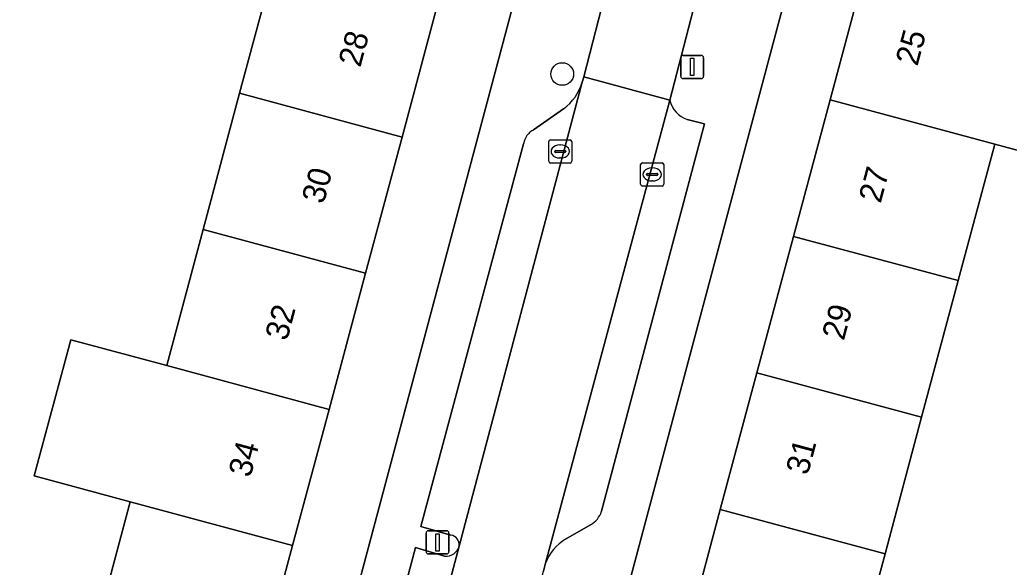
# Model space of a CAD drawing. Extents: x 163683 to 164494, y 382709 to 383872.
# Drawn here: x 163796.88 to 163839.7, y 383208.04 to 383231.71 of the extents above; entities that cross this region are included whole.
import ezdxf

# ---------------------------------------------------------------- set-up
doc = ezdxf.new("R2010")
doc.units = 0
for name, color, linetype in [('IMGEO_Boom', 7, 'Continuous'), ('IMGEO_Erf', 7, 'Continuous'), ('IMGEO_Kolk', 7, 'Continuous'), ('IMGEO_Lichtmast', 7, 'Continuous'), ('IMGEO_Pand', 7, 'Continuous'), ('IMGEO_Pand_nummerreeks', 7, 'Continuous'), ('IMGEO_Parkeervlak_open', 7, 'Continuous'), ('IMGEO_Rijbaan_lokaal_open', 7, 'Continuous'), ('IMGEO_Voetpad_open', 7, 'Continuous')]:
    doc.layers.add(name, color=color, linetype=linetype)

msp = doc.modelspace()

# ---------------------------------------------------------------- linework, layer by layer
at = {"layer": 'IMGEO_Boom'}
msp.add_circle((163820.356, 383229.363), 0.489, dxfattribs=at)
at = {"layer": 'IMGEO_Erf'}
for points in [[(163824.418, 383255.554), (163821.399, 383256.366), (163819.738, 383250.188), (163819.688, 383250), (163818.159, 383244.3), (163816.58, 383238.412), (163815.001, 383232.525), (163813.422, 383226.636), (163811.843, 383220.749), (163810.264, 383214.861), (163808.685, 383208.973), (163807.105, 383203.085), (163805.526, 383197.197), (163803.947, 383191.309), (163802.367, 383185.418), (163804.645, 383184.81)], [(163805.373, 383185.139), (163805.809, 383185.829), (163824.418, 383255.554)], [(163827.195, 383210.532), (163828.779, 383216.436), (163830.363, 383222.339), (163831.947, 383228.242), (163833.569, 383234.29), (163830.648, 383235.069), (163829.711, 383231.555), (163816.591, 383182.375)], [(163795.348, 383187.3), (163796.928, 383193.198), (163798.505, 383199.087), (163800.082, 383204.975), (163801.659, 383210.864), (163797.498, 383211.984), (163799.082, 383217.87), (163803.236, 383216.752), (163804.813, 383222.641), (163806.39, 383228.529), (163807.967, 383234.418)], [(163841.703, 383225.626), (163839.075, 383226.331), (163837.491, 383220.427), (163835.907, 383214.524), (163834.324, 383208.621), (163832.74, 383202.718), (163831.156, 383196.814), (163829.573, 383190.911), (163827.989, 383185.008), (163826.366, 383178.959), (163839.073, 383175.562), (163839.771, 383178.058), (163836.932, 383178.852), (163837.909, 383182.348), (163838.882, 383185.825), (163841.721, 383185.031)], [(163817.17, 383181.426), (163819.238, 383180.871), (163820.861, 383186.919), (163822.444, 383192.823), (163824.028, 383198.725), (163825.612, 383204.629), (163827.195, 383210.532)]]:
    msp.add_lwpolyline(points, dxfattribs=at)
at = {"layer": 'IMGEO_Kolk'}
for p, q in [((163819.769, 383225.588), (163819.769, 383226.44)), ((163819.844, 383226.514), (163820.696, 383226.514)), ((163820.77, 383226.44), (163820.77, 383225.588)), ((163820.028, 383226.008), (163820.028, 383226.02)), ((163820.466, 383225.971), (163820.068, 383225.971)), ((163820.071, 383226.057), (163820.469, 383226.057)), ((163820.257, 383226.294), (163820.282, 383226.294)), ((163820.512, 383226.02), (163820.512, 383226.008)), ((163820.696, 383225.514), (163819.844, 383225.514)), ((163820.28, 383225.734), (163820.255, 383225.734)), ((163823.823, 383225.52), (163824.675, 383225.52)), ((163823.748, 383224.594), (163823.748, 383225.446)), ((163824.05, 383225.063), (163824.448, 383225.063)), ((163824.236, 383225.3), (163824.261, 383225.3)), ((163824.749, 383225.446), (163824.749, 383224.594)), ((163824.007, 383225.014), (163824.007, 383225.026)), ((163824.445, 383224.977), (163824.047, 383224.977)), ((163824.259, 383224.74), (163824.234, 383224.74)), ((163824.491, 383225.026), (163824.491, 383225.014)), ((163824.675, 383224.52), (163823.823, 383224.52))]:
    msp.add_line(p, q, dxfattribs=at)
for points in [[(163819.769, 383225.588), (163819.769, 383226.44)], [(163819.844, 383226.514), (163820.696, 383226.514)], [(163820.77, 383226.44), (163820.77, 383225.588)], [(163820.696, 383225.514), (163819.844, 383225.514)], [(163823.823, 383225.52), (163824.675, 383225.52)], [(163823.748, 383224.594), (163823.748, 383225.446)], [(163824.749, 383225.446), (163824.749, 383224.594)], [(163824.675, 383224.52), (163823.823, 383224.52)]]:
    msp.add_lwpolyline(points, dxfattribs=at)
for centre, radius, start, end in [((163819.846, 383226.438), 0.0765, 91.552, 178.448), ((163819.846, 383226.438), 0.0765, 91.552, 178.448), ((163820.694, 383226.438), 0.0765, 1.552, 88.448), ((163820.694, 383226.438), 0.0765, 1.552, 88.448), ((163820.068, 383226.017), 0.0403, 85.8775, 175.7526), ((163820.065, 383226.007), 0.0366, 178.938, 274.7102), ((163820.469, 383226.014), 0.043, 264.8664, 352.4533), ((163820.473, 383226.019), 0.0386, 1.7309, 96.639), ((163819.846, 383225.59), 0.0765, 181.552, 268.448), ((163819.846, 383225.59), 0.0765, 181.552, 268.448), ((163820.694, 383225.59), 0.0765, 271.552, 358.448), ((163820.694, 383225.59), 0.0765, 271.552, 358.448), ((163823.825, 383225.444), 0.0765, 91.552, 178.448), ((163823.825, 383225.444), 0.0765, 91.552, 178.448), ((163824.673, 383225.444), 0.0765, 1.552, 88.448), ((163824.673, 383225.444), 0.0765, 1.552, 88.448), ((163824.047, 383225.023), 0.0403, 85.8775, 175.7526), ((163824.452, 383225.025), 0.0386, 1.7309, 96.639), ((163824.044, 383225.013), 0.0366, 178.938, 274.7102), ((163824.448, 383225.02), 0.043, 264.8664, 352.4533), ((163823.825, 383224.596), 0.0765, 181.552, 268.448), ((163823.825, 383224.596), 0.0765, 181.552, 268.448), ((163824.673, 383224.596), 0.0765, 271.552, 358.448), ((163824.673, 383224.596), 0.0765, 271.552, 358.448)]:
    msp.add_arc(centre, radius, start, end, dxfattribs=at)
for centre, major_axis, ratio, start_param, end_param in [((163820.256, 383226.014), (-0.387, 0.002), 0.722429, 4.712389, 7.853982), ((163820.281, 383226.014), (-0.39, 0.002), 0.717154, 1.570796, 4.712389), ((163824.235, 383225.02), (-0.387, 0.002), 0.722429, 4.712389, 7.853982), ((163824.26, 383225.02), (-0.39, 0.002), 0.717154, 1.570796, 4.712389)]:
    msp.add_ellipse(centre, major_axis=major_axis, ratio=ratio, start_param=start_param, end_param=end_param, dxfattribs=at)
at = {"layer": 'IMGEO_Lichtmast'}
for p, q in [((163825.482, 383229.268), (163825.482, 383230.068)), ((163825.482, 383230.068), (163825.482, 383229.268)), ((163825.582, 383230.168), (163826.372, 383230.168)), ((163826.372, 383230.168), (163825.582, 383230.168)), ((163826.472, 383230.068), (163826.472, 383229.268)), ((163826.472, 383229.268), (163826.472, 383230.068)), ((163826.372, 383229.168), (163825.582, 383229.168)), ((163825.582, 383229.168), (163826.372, 383229.168)), ((163814.46, 383208.711), (163814.46, 383209.511)), ((163814.46, 383209.511), (163814.46, 383208.711)), ((163814.56, 383209.611), (163815.35, 383209.611)), ((163815.35, 383209.611), (163814.56, 383209.611)), ((163815.45, 383209.511), (163815.45, 383208.711)), ((163815.45, 383208.711), (163815.45, 383209.511)), ((163815.35, 383208.611), (163814.56, 383208.611)), ((163814.56, 383208.611), (163815.35, 383208.611))]:
    msp.add_line(p, q, dxfattribs=at)
for points in [[(163825.902, 383230.043), (163826.052, 383230.043), (163826.052, 383229.293), (163825.902, 383229.293), (163825.902, 383230.043)], [(163814.88, 383209.486), (163815.03, 383209.486), (163815.03, 383208.736), (163814.88, 383208.736), (163814.88, 383209.486)]]:
    msp.add_lwpolyline(points, dxfattribs=at)
for centre, start, end in [((163825.582, 383230.068), 90, 180), ((163825.582, 383230.068), 90, 180), ((163826.372, 383230.068), 0, 90), ((163826.372, 383230.068), 360, 90), ((163825.582, 383229.268), 180, 270), ((163825.582, 383229.268), 180, 270), ((163826.372, 383229.268), 270, 0), ((163826.372, 383229.268), 270, 0), ((163814.56, 383209.511), 90, 180), ((163814.56, 383209.511), 90, 180), ((163815.35, 383209.511), 0, 90), ((163815.35, 383209.511), 360, 90), ((163814.56, 383208.711), 180, 270), ((163814.56, 383208.711), 180, 270), ((163815.35, 383208.711), 270, 0), ((163815.35, 383208.711), 270, 0)]:
    msp.add_arc(centre, 0.1, start, end, dxfattribs=at)
at = {"layer": 'IMGEO_Pand'}
for points in [[(163807.967, 383234.418), (163806.39, 383228.529), (163813.422, 383226.636), (163815.001, 383232.525)], [(163839.075, 383226.331), (163841.703, 383225.626), (163843.325, 383231.674), (163840.697, 383232.378), (163838.399, 383232.994), (163833.569, 383234.29), (163831.947, 383228.242)], [(163813.422, 383226.636), (163806.39, 383228.529), (163804.813, 383222.641), (163811.843, 383220.749)], [(163839.075, 383226.331), (163831.947, 383228.242), (163830.363, 383222.339), (163837.491, 383220.427)], [(163811.843, 383220.749), (163804.813, 383222.641), (163803.236, 383216.752), (163810.264, 383214.861)], [(163828.779, 383216.436), (163835.907, 383214.524), (163837.491, 383220.427), (163830.363, 383222.339)], [(163810.264, 383214.861), (163803.236, 383216.752), (163799.082, 383217.87), (163797.498, 383211.984), (163801.659, 383210.864), (163808.685, 383208.973)], [(163834.324, 383208.621), (163835.907, 383214.524), (163828.779, 383216.436), (163827.195, 383210.532)], [(163801.659, 383210.864), (163800.082, 383204.975), (163807.105, 383203.085), (163808.685, 383208.973)], [(163834.324, 383208.621), (163827.195, 383210.532), (163825.612, 383204.629), (163832.74, 383202.718)]]:
    msp.add_lwpolyline(points, close=True, dxfattribs=at)
at = {"layer": 'IMGEO_Parkeervlak_open'}
for points in [[(163815.899, 383208.952), (163821.224, 383229.007)], [(163825.009, 383228.231), (163819.632, 383208.209)], [(163820.405, 383227.862), (163819.118, 383226.956)], [(163822.055, 383210.455), (163826.517, 383227.212), (163825.762, 383227.397)], [(163818.681, 383226.35), (163814.242, 383209.793), (163815.535, 383209.42)], [(163820.496, 383209.249), (163821.58, 383209.869)], [(163815.264, 383208.517), (163814.001, 383208.882), (163807.499, 383184.421), (163806.584, 383180.516)], [(163807.857, 383177.043), (163808.9, 383182.594), (163815.899, 383208.952)]]:
    msp.add_lwpolyline(points, dxfattribs=at)
for centre, radius, start, end in [((163819.16, 383229.618), 2.152, 305.3373, 343.5117), ((163826.167, 383228.519), 1.193, 193.9861, 250.1702), ((163819.515, 383226.209), 0.845, 117.9801, 170.4275), ((163821.087, 383210.754), 1.013, 299.1061, 342.8388), ((163815.48, 383209.002), 0.422, 353.1949, 82.5551), ((163821.557, 383207.488), 2.056, 121.0822, 159.4803), ((163815.323, 383209.112), 0.598, 264.3758, 344.4496)]:
    msp.add_arc(centre, radius, start, end, dxfattribs=at)
at = {"layer": 'IMGEO_Rijbaan_lokaal_open'}
for points in [[(163821.284, 383229.236), (163825.009, 383228.231), (163826.124, 383232.512), (163822.389, 383233.509), (163822.316, 383233.238)], [(163819.538, 383207.865), (163819.632, 383208.209), (163825.009, 383228.231), (163821.284, 383229.236), (163821.257, 383229.134), (163821.224, 383229.007), (163815.899, 383208.952), (163808.9, 383182.594), (163807.857, 383177.043), (163807.843, 383176.959), (163805.285, 383161.544), (163808.901, 383160.938), (163811.944, 383178.556), (163812.512, 383181.477), (163812.535, 383181.595), (163813.306, 383184.59)]]:
    msp.add_lwpolyline(points, close=True, dxfattribs=at)
at = {"layer": 'IMGEO_Voetpad_open'}
for points in [[(163839.135, 383310.697), (163825.204, 383258.5), (163824.418, 383255.554), (163805.809, 383185.829), (163804.95, 383182.609), (163804.884, 383182.205), (163800.972, 383158.294), (163804.663, 383157.957), (163805.285, 383161.544), (163804.9, 383162.407), (163804.142, 383163.521)], [(163810.692, 383162.593), (163809.541, 383161.632), (163808.901, 383160.938), (163808.29, 383157.426), (163812.287, 383156.459), (163816.096, 383179.394), (163816.591, 383182.375), (163829.711, 383231.555), (163830.648, 383235.069), (163831.4, 383237.888), (163850.058, 383307.826)], [(163827.204, 383236.582), (163826.124, 383232.512), (163825.009, 383228.231)], [(163821.224, 383229.007), (163821.257, 383229.134), (163821.284, 383229.236), (163822.316, 383233.238), (163822.389, 383233.509), (163822.024, 383234.515), (163821.387, 383235.492)], [(163819.118, 383226.956), (163820.405, 383227.862)], [(163825.762, 383227.397), (163826.517, 383227.212), (163822.055, 383210.455)], [(163815.535, 383209.42), (163814.242, 383209.793), (163818.681, 383226.35)], [(163821.58, 383209.869), (163820.496, 383209.249)], [(163806.584, 383180.516), (163807.499, 383184.421), (163814.001, 383208.882), (163815.264, 383208.517)], [(163819.632, 383208.209), (163819.538, 383207.865)]]:
    msp.add_lwpolyline(points, dxfattribs=at)
for centre, radius, start, end in [((163819.16, 383229.618), 2.152, 305.3373, 343.5117), ((163826.167, 383228.519), 1.193, 193.9861, 250.1702), ((163819.515, 383226.209), 0.845, 117.9801, 170.4275), ((163821.087, 383210.754), 1.013, 299.1061, 342.8388), ((163815.48, 383209.002), 0.422, 353.1949, 82.5551), ((163821.557, 383207.488), 2.056, 121.0822, 159.4803), ((163815.323, 383209.112), 0.598, 264.3758, 344.4496)]:
    msp.add_arc(centre, radius, start, end, dxfattribs=at)

# ---------------------------------------------------------------- texts
at = {"layer": 'IMGEO_Pand_nummerreeks'}
for s, rotation, p in [('28', 74.9838, (163811.615, 383229.619)), ('25', 74.9826, (163835.726, 383229.675)), ('30', 74.9838, (163810.029, 383223.707)), ('27', 74.9826, (163834.133, 383223.739)), ('32', 74.9838, (163808.442, 383217.788)), ('29', 74.9826, (163832.541, 383217.804)), ('34', 74.983, (163806.855, 383211.879)), ('31', 74.9826, (163830.979, 383211.978))]:
    msp.add_text(s, height=1, rotation=rotation, dxfattribs=at).set_placement(p)

doc.saveas('drawing.dxf')
